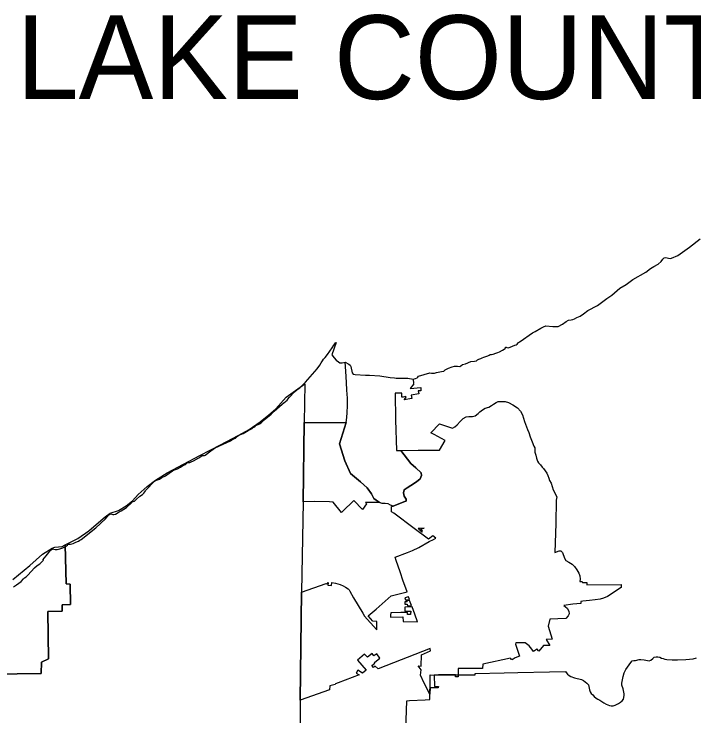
# Model space of a CAD drawing. Extents: x 0 to 42.4, y 0 to 22.
# Drawn here: x 39.951 to 41.088, y 19.771 to 20.945 of the extents above; entities that cross this region are included whole.
import ezdxf

# ---------------------------------------------------------------- set-up
doc = ezdxf.new("R2010")
doc.units = 0
for name, color, linetype in [('Default', 7, 'Continuous'), ('GM_X_Corporation', 7, 'Continuous'), ('GM_X_County', 7, 'Continuous')]:
    doc.layers.add(name, color=color, linetype=linetype)

msp = doc.modelspace()

# ---------------------------------------------------------------- linework, layer by layer
at = {"layer": 'GM_X_Corporation'}
for points in [[(40.505, 20.3629), (40.5109, 20.3596), (40.513, 20.358), (40.5144, 20.3555), (40.5165, 20.3452), (40.5184, 20.3429), (40.5214, 20.342), (40.5388, 20.3411), (40.5456, 20.341), (40.5628, 20.3398), (40.5798, 20.3373), (40.5872, 20.3368), (40.5899, 20.3358), (40.6098, 20.3361), (40.6186, 20.3341), (40.6191, 20.3269), (40.6198, 20.3264), (40.6134, 20.3188), (40.6311, 20.3204), (40.6314, 20.315), (40.6284, 20.3148), (40.6269, 20.3146), (40.6279, 20.3097), (40.6151, 20.3074), (40.6162, 20.302), (40.6037, 20.2996), (40.6068, 20.3044), (40.6055, 20.3051), (40.6018, 20.3045), (40.5996, 20.3044), (40.5994, 20.3112), (40.5882, 20.3111), (40.589, 20.2666), (40.5905, 20.2152), (40.5981, 20.2152), (40.6147, 20.1933), (40.6231, 20.1861), (40.6317, 20.1778), (40.6322, 20.1735), (40.6302, 20.1678), (40.6243, 20.1629), (40.6145, 20.1564), (40.6084, 20.1526), (40.6033, 20.1493), (40.6024, 20.1446), (40.6035, 20.1389), (40.6065, 20.134), (40.6068, 20.1307), (40.6056, 20.1302), (40.5849, 20.122), (40.5806, 20.1237), (40.5766, 20.1259), (40.5715, 20.1265), (40.5666, 20.1267), (40.5621, 20.1284), (40.553, 20.1351), (40.5487, 20.1426), (40.5418, 20.1527), (40.5305, 20.1628), (40.5138, 20.1767), (40.504, 20.198), (40.4956, 20.2261), (40.5063, 20.2619), (40.5076, 20.27), (40.5083, 20.2785), (40.5085, 20.2896), (40.5086, 20.3024), (40.5077, 20.3162), (40.5072, 20.329), (40.5066, 20.3381), (40.5059, 20.3478)], [(40.5981, 20.2152), (40.6268, 20.2155), (40.6408, 20.2155), (40.6511, 20.2156), (40.6626, 20.2157), (40.6718, 20.2316), (40.6538, 20.2416), (40.6482, 20.2447), (40.6625, 20.2599), (40.684, 20.2527), (40.6879, 20.2549), (40.6919, 20.2579), (40.6969, 20.2635), (40.7021, 20.2685), (40.7068, 20.2715), (40.7113, 20.2717), (40.7175, 20.2722), (40.7218, 20.2732), (40.7272, 20.2767), (40.7298, 20.2795), (40.7341, 20.283), (40.7388, 20.286), (40.7447, 20.2875), (40.7494, 20.2905), (40.7528, 20.2924), (40.7573, 20.2955), (40.7603, 20.2969), (40.7657, 20.2972), (40.772, 20.2969), (40.778, 20.2954), (40.7849, 20.2916), (40.7926, 20.2862), (40.7976, 20.2806), (40.801, 20.2746), (40.8043, 20.2636), (40.8079, 20.2544), (40.8097, 20.2502), (40.8118, 20.2453), (40.814, 20.2378), (40.8172, 20.2298), (40.8202, 20.2221), (40.822, 20.2193), (40.8219, 20.216), (40.822, 20.2121), (40.8234, 20.2074), (40.8247, 20.2022), (40.8261, 20.1975), (40.8278, 20.1945), (40.831, 20.1909), (40.8338, 20.1874), (40.8362, 20.185), (40.8392, 20.1812), (40.842, 20.1771), (40.8433, 20.1734), (40.8454, 20.1691), (40.8465, 20.1648), (40.8492, 20.1606), (40.8522, 20.1493), (40.8588, 20.1376), (40.8575, 20.1319), (40.8568, 20.093), (40.8554, 20.0445), (40.8625, 20.0475), (40.8651, 20.0476), (40.8679, 20.0448), (40.8715, 20.0354), (40.8738, 20.0313), (40.8785, 20.0283), (40.8844, 20.0252), (40.8881, 20.021), (40.8917, 20.0158), (40.8955, 20.0101), (40.8972, 20.0055), (40.8974, 19.9998), (40.8969, 19.9962), (40.9009, 19.996), (40.9012, 19.9946), (40.9089, 19.9945), (40.9088, 19.9908), (40.9658, 19.9914), (40.966, 19.9861), (40.9433, 19.971), (40.9368, 19.9685), (40.9311, 19.9665), (40.9225, 19.9655), (40.9129, 19.9644), (40.9022, 19.963), (40.8985, 19.9625), (40.8984, 19.9595), (40.8851, 19.9583), (40.87, 19.9559), (40.8757, 19.9516), (40.8784, 19.9464), (40.8791, 19.9423), (40.8775, 19.9385), (40.8735, 19.9342), (40.8471, 19.933), (40.8438, 19.9214), (40.8508, 19.8997), (40.8406, 19.899), (40.8467, 19.8891), (40.8365, 19.8893), (40.8284, 19.8797), (40.8249, 19.8835), (40.8243, 19.8826), (40.8196, 19.879), (40.817, 19.883), (40.8122, 19.8888), (40.8055, 19.8937), (40.7902, 19.8938), (40.7895, 19.8916), (40.7962, 19.8712), (40.789, 19.8687), (40.784, 19.8654), (40.7839, 19.8655), (40.7837, 19.8657), (40.7835, 19.8658), (40.7832, 19.8659), (40.783, 19.866), (40.7828, 19.866), (40.7827, 19.8661), (40.7825, 19.8661), (40.7824, 19.8661), (40.7823, 19.8661), (40.782, 19.8661), (40.7818, 19.8661), (40.7817, 19.8661), (40.7815, 19.866), (40.7811, 19.868), (40.7347, 19.8582), (40.7345, 19.8505), (40.6934, 19.8508), (40.6936, 19.8368), (40.6891, 19.8367), (40.689, 19.8399), (40.661, 19.8399), (40.6535, 19.8398), (40.6539, 19.8208), (40.6606, 19.8208), (40.6605, 19.8185), (40.6473, 19.8183), (40.6466, 19.8195), (40.6465, 19.8076), (40.6368, 19.8262), (40.6308, 19.8394), (40.6317, 19.8487), (40.6267, 19.8552), (40.6316, 19.8549), (40.6322, 19.8737), (40.6474, 19.8802), (40.647, 19.8842), (40.5597, 19.85), (40.5551, 19.8549), (40.5524, 19.8525), (40.5496, 19.8556), (40.5544, 19.8597), (40.5536, 19.8606), (40.5629, 19.868), (40.5577, 19.8754), (40.5529, 19.8721), (40.5501, 19.8756), (40.542, 19.8694), (40.5374, 19.8746), (40.5255, 19.8645), (40.5398, 19.8481), (40.534, 19.843), (40.5261, 19.8481), (40.523, 19.8432), (40.528, 19.84), (40.4934, 19.8267), (40.4887, 19.8249), (40.4882, 19.8242), (40.4793, 19.8217), (40.4791, 19.8216), (40.4789, 19.8152), (40.4296, 19.7976), (40.4317, 19.9782), (40.4733, 19.9929), (40.4738, 19.9924), (40.4748, 19.993), (40.4756, 19.9935), (40.4753, 19.9941), (40.4762, 19.9946), (40.4762, 19.9937), (40.476, 19.9898), (40.482, 19.9896), (40.4823, 19.9947), (40.4887, 19.9936), (40.4962, 19.9911), (40.4966, 19.991), (40.5016, 19.9889), (40.5053, 19.9866), (40.5099, 19.9837), (40.5113, 19.9824), (40.5124, 19.9801), (40.5189, 19.969), (40.5341, 19.943), (40.5364, 19.9392), (40.5368, 19.9387), (40.5577, 19.9152), (40.5578, 19.9295), (40.5509, 19.9296), (40.5431, 19.939), (40.5567, 19.9498), (40.5819, 19.9721), (40.6084, 19.9787), (40.6063, 19.9848), (40.602, 19.9968), (40.5968, 20.0122), (40.5903, 20.0313), (40.5884, 20.0368), (40.6088, 20.0445), (40.6176, 20.0481), (40.6279, 20.0531), (40.6452, 20.0628), (40.6524, 20.0662), (40.6565, 20.0685), (40.6511, 20.0727), (40.6442, 20.067), (40.6204, 20.085), (40.5864, 20.1103), (40.5822, 20.1128), (40.5821, 20.1213), (40.5849, 20.122), (40.6056, 20.1302), (40.6068, 20.1307), (40.6065, 20.134), (40.6035, 20.1389), (40.6024, 20.1446), (40.6033, 20.1493), (40.6084, 20.1526), (40.6145, 20.1564), (40.6243, 20.1629), (40.6302, 20.1678), (40.6322, 20.1735), (40.6317, 20.1778), (40.6231, 20.1861), (40.6147, 20.1933)], [(40.4362, 20.262), (40.5063, 20.2619), (40.4956, 20.2261), (40.504, 20.198), (40.5138, 20.1767), (40.5305, 20.1628), (40.5418, 20.1527), (40.5487, 20.1426), (40.553, 20.1351), (40.5621, 20.1284), (40.5389, 20.1284), (40.5407, 20.1261), (40.534, 20.1166), (40.5194, 20.1313), (40.5004, 20.113), (40.4985, 20.1113), (40.4846, 20.1285), (40.4786, 20.1291), (40.4544, 20.1297), (40.4345, 20.1294)], [(40.6267, 20.085), (40.6302, 20.0814), (40.6327, 20.0788), (40.6343, 20.0803), (40.6312, 20.0841), (40.6367, 20.0854), (40.6299, 20.085)], [(40.6054, 19.9657), (40.6121, 19.9658), (40.6104, 19.9707), (40.6044, 19.9687)], [(40.6155, 19.9558), (40.6125, 19.9645), (40.6069, 19.9644), (40.6083, 19.9624), (40.6043, 19.9623), (40.6043, 19.9584), (40.6083, 19.9585), (40.6089, 19.9557)], [(40.6015, 19.9292), (40.6259, 19.929), (40.6213, 19.9416), (40.6169, 19.9536), (40.6047, 19.9534), (40.6046, 19.9463), (40.6145, 19.9463), (40.6144, 19.9443), (40.6141, 19.9437), (40.6141, 19.9412), (40.6089, 19.9412), (40.6089, 19.9441), (40.5981, 19.9443), (40.5812, 19.9436), (40.5808, 19.9399), (40.5808, 19.9367), (40.6014, 19.9369)]]:
    msp.add_lwpolyline(points, close=True, dxfattribs=at)
for points in [[(39.8673, 19.8414), (39.9568, 19.8419), (39.997, 19.8423), (39.9971, 19.8613), (40.0089, 19.867), (40.0081, 19.9459), (40.0319, 19.9467), (40.032, 19.957), (40.0461, 19.9575), (40.0454, 19.9917), (40.0384, 19.992), (40.0367, 20.0573), (40.0582, 20.0681), (40.0764, 20.081), (40.0967, 20.0981), (40.1035, 20.1043), (40.112, 20.1101), (40.1262, 20.1151), (40.1388, 20.1226), (40.1495, 20.1312), (40.1591, 20.1418), (40.1737, 20.1548), (40.1877, 20.1657), (40.2073, 20.1777), (40.2622, 20.2069), (40.2963, 20.2247), (40.3258, 20.2404), (40.3443, 20.2502), (40.3626, 20.2629), (40.3772, 20.2745), (40.3892, 20.285), (40.4063, 20.3043), (40.4219, 20.3152), (40.4374, 20.3264), (40.4362, 20.262), (40.4345, 20.1294), (40.4317, 19.9782), (40.4296, 19.7976), (40.4296, 19.7283)], [(39.9494, 19.9994), (39.9781, 20.023), (39.9992, 20.0418), (40.0151, 20.0519), (40.0198, 20.0534), (40.0318, 20.0544), (40.0367, 20.0573), (40.0384, 19.992), (40.0454, 19.9917), (40.0461, 19.9575), (40.032, 19.957), (40.0319, 19.9467), (40.0081, 19.9459), (40.0089, 19.867), (39.9971, 19.8613), (39.997, 19.8423), (39.9568, 19.8419), (39.8673, 19.8414)], [(40.6056, 19.7313), (40.6078, 19.7969), (40.6126, 19.7971), (40.6385, 19.7983), (40.6465, 19.7989), (40.6465, 19.8076), (40.6465, 19.8137), (40.6466, 19.8195), (40.6468, 19.8399), (40.6535, 19.8398), (40.661, 19.8399), (40.689, 19.8399), (40.7222, 19.8399), (40.7222, 19.8423), (40.7707, 19.8436), (40.7932, 19.8441), (40.8465, 19.8449), (40.8731, 19.8459), (40.874, 19.8438), (40.8764, 19.8411), (40.8792, 19.8388), (40.8822, 19.8374), (40.8881, 19.8354), (40.9, 19.8325), (40.903, 19.8308), (40.9086, 19.8263), (40.9113, 19.8234), (40.9123, 19.8207), (40.9132, 19.8149), (40.9142, 19.812), (40.9157, 19.8092), (40.9185, 19.8067), (40.9211, 19.8038), (40.9244, 19.8012), (40.9271, 19.7993), (40.9302, 19.7977), (40.9371, 19.7935), (40.9408, 19.791), (40.9437, 19.7898), (40.9465, 19.7891), (40.9496, 19.7886), (40.9525, 19.7886), (40.9559, 19.7896), (40.9591, 19.7909), (40.9618, 19.7924), (40.9649, 19.7944), (40.9678, 19.7968), (40.9698, 19.7995), (40.9708, 19.8054), (40.9708, 19.8083), (40.9706, 19.8111), (40.9695, 19.8166), (40.9674, 19.8231), (40.9673, 19.8262), (40.9692, 19.8375), (40.971, 19.8436), (40.9739, 19.8491), (40.9821, 19.8609), (40.9844, 19.8638), (40.9873, 19.8643), (40.9902, 19.8641), (40.9959, 19.8658), (40.9987, 19.866), (41.0044, 19.8654), (41.0131, 19.8636), (41.0159, 19.8648), (41.0187, 19.8677), (41.0214, 19.8695), (41.0245, 19.8704), (41.0274, 19.8704), (41.0306, 19.8695), (41.0333, 19.8682), (41.0361, 19.8673), (41.0388, 19.8666), (41.0421, 19.866), (41.0511, 19.8652), (41.06, 19.8652), (41.0741, 19.8659), (41.0866, 19.867), (41.0921, 19.8685)]]:
    msp.add_lwpolyline(points, dxfattribs=at)
at = {"layer": 'GM_X_County'}
msp.add_lwpolyline([(39.9505, 19.9875), (39.9557, 19.9906), (39.9633, 19.9961), (39.9672, 20.0004), (39.9688, 20.0022), (39.9719, 20.0042), (39.9746, 20.007), (39.9859, 20.0191), (39.9899, 20.0231), (39.9943, 20.0259), (39.9982, 20.0293), (40.0002, 20.0312), (40.0005, 20.0318), (40.0001, 20.0321), (39.9997, 20.0323), (40.0049, 20.0391), (40.0096, 20.0446), (40.0111, 20.047), (40.0134, 20.0491), (40.0158, 20.0507), (40.0202, 20.0496), (40.0233, 20.0498), (40.0281, 20.0506), (40.033, 20.0523), (40.0364, 20.0539), (40.0391, 20.0555), (40.0408, 20.057), (40.0416, 20.0578), (40.0432, 20.0584), (40.0456, 20.0586), (40.0503, 20.0594), (40.0545, 20.0619), (40.0593, 20.0638), (40.0612, 20.0651), (40.0638, 20.0665), (40.0685, 20.0704), (40.0831, 20.0819), (40.0882, 20.0861), (40.1042, 20.1011), (40.11, 20.1074), (40.1117, 20.1087), (40.1131, 20.1093), (40.1163, 20.1081), (40.118, 20.108), (40.1209, 20.1087), (40.1256, 20.1115), (40.1304, 20.1142), (40.1395, 20.1201), (40.1476, 20.1278), (40.149, 20.1294), (40.1508, 20.1301), (40.153, 20.1307), (40.1558, 20.1332), (40.1619, 20.1386), (40.1663, 20.1418), (40.1683, 20.1439), (40.1701, 20.1458), (40.1709, 20.1477), (40.1715, 20.1488), (40.173, 20.1501), (40.1748, 20.1521), (40.1828, 20.1606), (40.1857, 20.1633), (40.1895, 20.1654), (40.1944, 20.1673), (40.1982, 20.17), (40.2044, 20.1729), (40.2105, 20.1775), (40.2155, 20.1806), (40.2198, 20.1828), (40.2244, 20.1842), (40.2295, 20.1874), (40.2338, 20.19), (40.2381, 20.1916), (40.2399, 20.1933), (40.241, 20.1946), (40.2422, 20.1953), (40.2452, 20.1953), (40.2477, 20.1959), (40.2512, 20.1978), (40.2602, 20.2028), (40.2639, 20.2051), (40.2661, 20.2065), (40.2681, 20.2067), (40.27, 20.2068), (40.271, 20.2072), (40.2731, 20.2092), (40.2781, 20.2129), (40.284, 20.2172), (40.2875, 20.2197), (40.301, 20.2255), (40.3133, 20.2315), (40.3156, 20.2328), (40.3166, 20.2334), (40.3189, 20.2344), (40.3216, 20.236), (40.3234, 20.2374), (40.3251, 20.2391), (40.3264, 20.2402), (40.3299, 20.2416), (40.3344, 20.2435), (40.3429, 20.2483), (40.3493, 20.2517), (40.3513, 20.2536), (40.3536, 20.2547), (40.3558, 20.2567), (40.3618, 20.2598), (40.3645, 20.2615), (40.3672, 20.2641), (40.3694, 20.2663), (40.3811, 20.276), (40.3859, 20.2807), (40.3998, 20.2925), (40.4078, 20.2995), (40.4113, 20.3039), (40.4203, 20.3131), (40.4242, 20.3163), (40.4288, 20.32), (40.4324, 20.3231), (40.4359, 20.3268), (40.4385, 20.3295), (40.4579, 20.3515), (40.4625, 20.3579), (40.4647, 20.3617), (40.4669, 20.3651), (40.4686, 20.3677), (40.4713, 20.3704), (40.4752, 20.3757), (40.4829, 20.3869), (40.4859, 20.3911), (40.4874, 20.3936), (40.4888, 20.3949), (40.4897, 20.3954), (40.4826, 20.3748), (40.4863, 20.3699), (40.4899, 20.3659), (40.4938, 20.3634), (40.496, 20.3617), (40.4996, 20.3619), (40.505, 20.3629), (40.5109, 20.3596), (40.513, 20.358), (40.5144, 20.3555), (40.5165, 20.3452), (40.5184, 20.3429), (40.5214, 20.342), (40.5388, 20.3411), (40.5456, 20.341), (40.5628, 20.3398), (40.5798, 20.3373), (40.5872, 20.3368), (40.5899, 20.3358), (40.6098, 20.3361), (40.6186, 20.3341), (40.6221, 20.3355), (40.625, 20.3368), (40.6263, 20.3377), (40.6272, 20.3391), (40.6463, 20.3452), (40.6491, 20.3444), (40.6507, 20.3443), (40.6519, 20.3441), (40.654, 20.3441), (40.6573, 20.3453), (40.6656, 20.347), (40.6697, 20.3478), (40.6722, 20.35), (40.6777, 20.3527), (40.6837, 20.355), (40.6876, 20.3559), (40.6924, 20.3562), (40.6965, 20.3553), (40.6982, 20.3564), (40.701, 20.3586), (40.7058, 20.3599), (40.7148, 20.364), (40.7212, 20.3644), (40.7242, 20.365), (40.7262, 20.3664), (40.7284, 20.3679), (40.7313, 20.3687), (40.7337, 20.3702), (40.7364, 20.3712), (40.7383, 20.3716), (40.7431, 20.3736), (40.7456, 20.3746), (40.7473, 20.3757), (40.7493, 20.3758), (40.7519, 20.3759), (40.7568, 20.3776), (40.7602, 20.3788), (40.763, 20.3803), (40.7678, 20.383), (40.7724, 20.3857), (40.7727, 20.3867), (40.773, 20.3877), (40.7736, 20.3881), (40.775, 20.3875), (40.7777, 20.3867), (40.7845, 20.3894), (40.7881, 20.3911), (40.7904, 20.392), (40.792, 20.3929), (40.7937, 20.3949), (40.7945, 20.3959), (40.7961, 20.3967), (40.7973, 20.3973), (40.8178, 20.412), (40.8223, 20.4141), (40.8316, 20.4196), (40.836, 20.4221), (40.84, 20.4234), (40.8517, 20.4226), (40.8606, 20.4225), (40.8679, 20.4261), (40.8744, 20.4307), (40.8783, 20.4331), (40.8826, 20.4338), (40.8855, 20.4342), (40.8882, 20.4354), (40.8918, 20.4376), (40.8974, 20.4397), (40.9029, 20.4437), (40.9105, 20.449), (40.9267, 20.4573), (40.942, 20.469), (40.9505, 20.475), (40.9641, 20.4863), (40.9746, 20.4927), (40.9857, 20.5009), (41.0075, 20.5133), (41.0151, 20.5195), (41.0204, 20.5225), (41.0279, 20.5265), (41.0328, 20.5312), (41.0358, 20.5349), (41.0368, 20.5363), (41.0378, 20.5374), (41.0403, 20.5377), (41.0479, 20.536), (41.0504, 20.5367), (41.0609, 20.5412), (41.0802, 20.5551), (41.0983, 20.5688)], dxfattribs=at)

# ---------------------------------------------------------------- texts
at = {"layer": 'Default'}
msp.add_text('LAKE COUNTY', height=0.14, dxfattribs=at).set_placement((39.9553, 20.8026))

doc.saveas('drawing.dxf')
